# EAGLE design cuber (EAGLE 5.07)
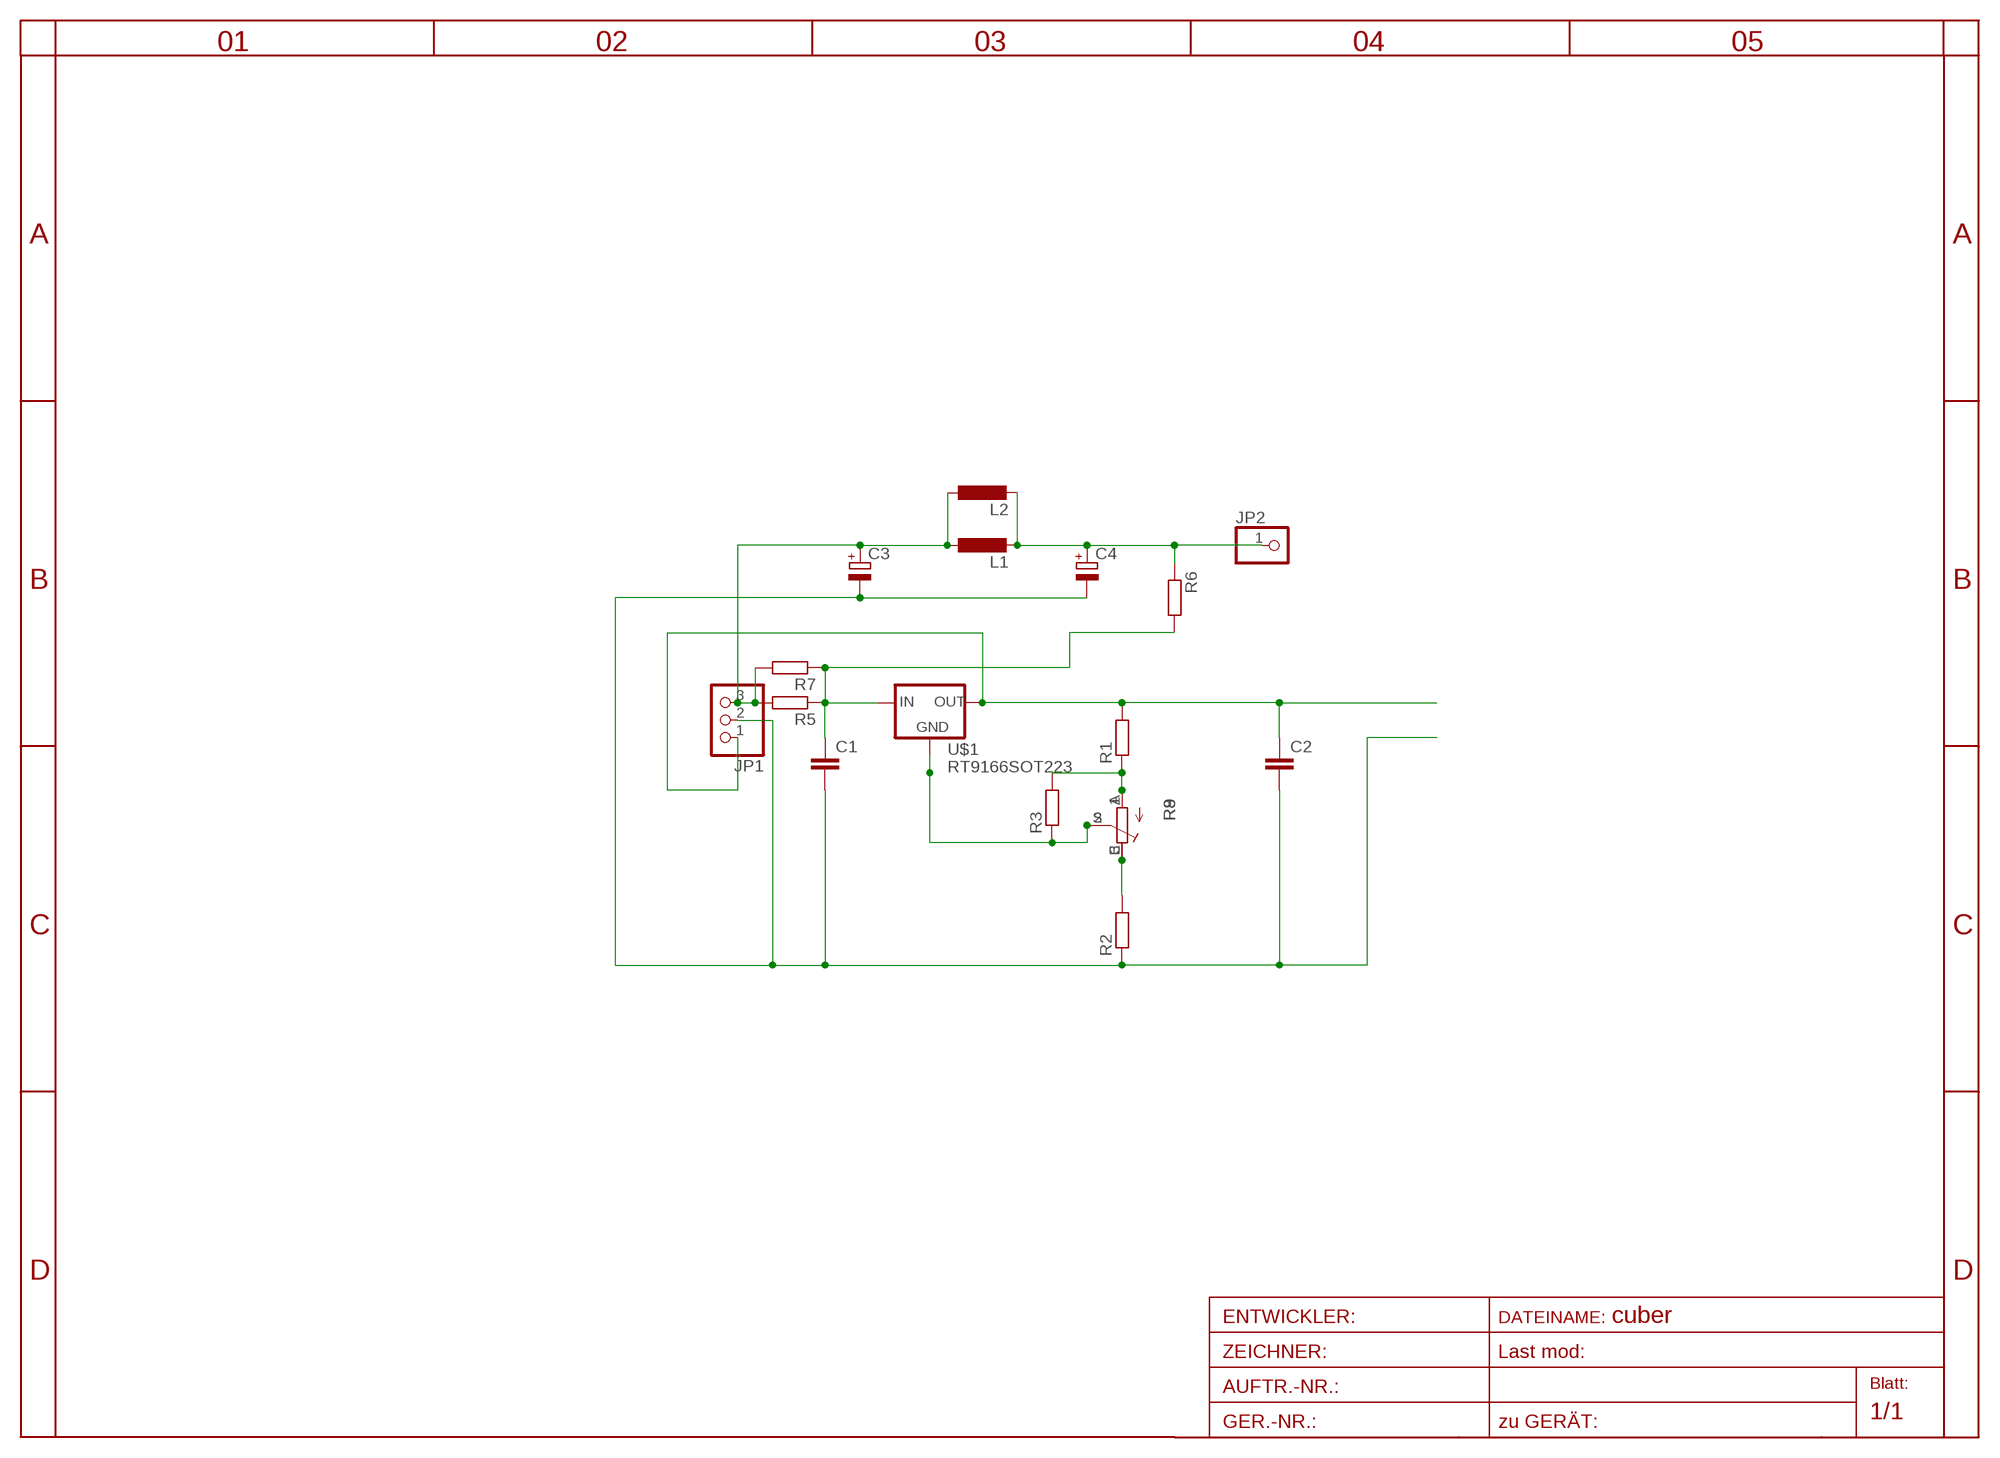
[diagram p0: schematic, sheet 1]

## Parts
C1  C-EUC1206  [C1206]
C2  C-EUC1206  [C1206]
C3  CPOL-EUE  [PANASONIC_E]
C4  CPOL-EUE  [PANASONIC_E]
JP1  PINHD-1X3  [1X03]
JP2  PINHD-1X11X0.4  [1X01]
L1  L-EUPIS2816  [PIS2816]
L2  L-EUOPEN  [OPEN5]
R1  R-EU_R0805  [R0805]
R2  R-EU_R0805  [R0805]
R3  R-EU_R0805  [R0805]
R5  R-EU_R0805  [R0805]
R6  R-EU_R0805  [R0805]
R7  R-EU_R0805  [R0805]
R8  TRIM_EU-RAND160  [RANDL]
R9  R-TRIMM3339P  [RTRIM3339P]
U$1  RT9166SOT223  [SOT223]

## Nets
ADJ: R3.1 R8.S R9.2(S) U$1.2(GND) U$1.4(GND1)
GND: C1.2 C2.2 C3.- C4.- JP1.2 R2.1
IN: C1.1 R5.1 R6.2 R7.1 U$1.3(IN)
N$1: C3.+ JP1.3 L1.1 L2.1 R5.2 R7.2
N$3: C4.+ JP2.1 L1.2 L2.2 R6.1
N$6: R2.2 R8.E R9.3(A)
N$7: R1.1 R3.2 R8.A R9.1(E)
OUT: C2.1 JP1.1 R1.2 U$1.1(OUT)

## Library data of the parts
C1 C2 = rcl:C-EU: CAPACITOR, European symbol
C3 C4 = rcl:CPOL-EU: POLARIZED CAPACITOR, European symbol
JP1 = pinhead:PINHD-1X3: PIN HEADER
JP2 = pinhead:PINHD-1X1: PIN HEADER
L1 L2 = rcl:L-EU: INDUCTOR, European symbol
R1-R3 R5-R7 = rcl:R-EU_: RESISTOR, European symbol
R8 = pot:TRIM_EU-: POTENTIOMETER
R9 = rcl:R-TRIMM: Trimm resistor
U$1 = v-reg:RT9166

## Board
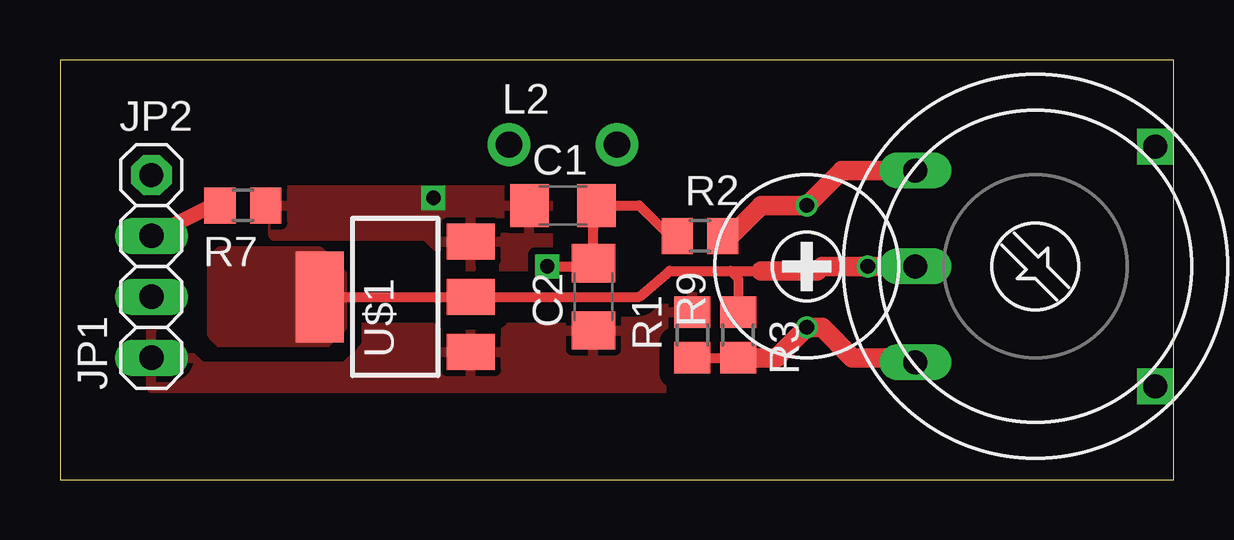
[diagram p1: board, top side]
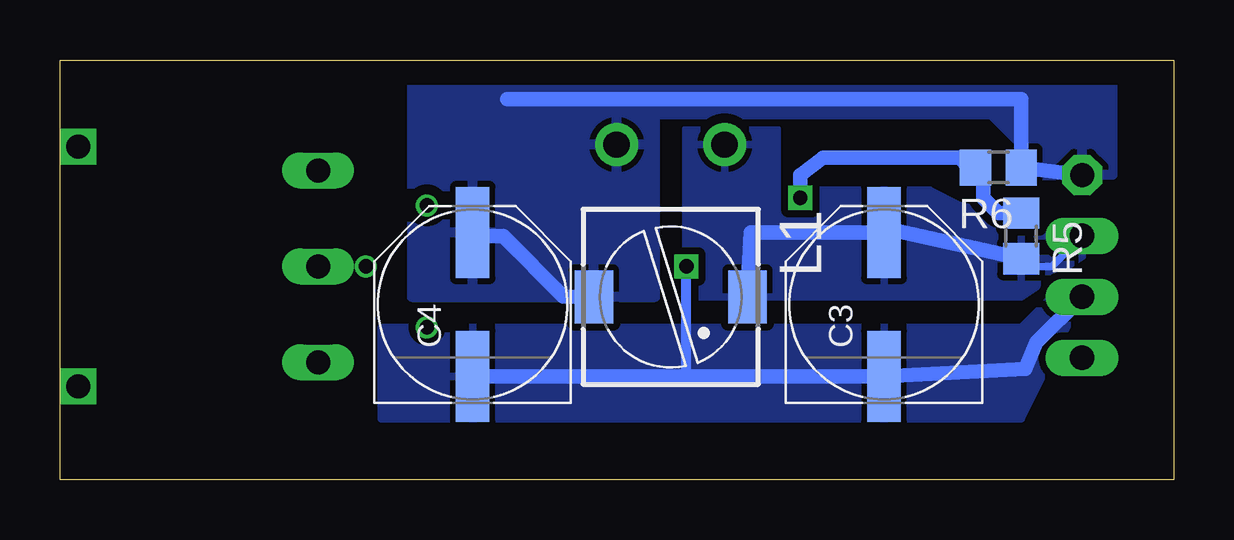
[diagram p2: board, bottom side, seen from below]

Size 46.4 x 17.5 mm. Coordinates in mm from the lower left corner, seen from the top.
Outline: 0,0 46.4,0 46.4,17.5 0,17.5 0,0
Copper layers (1*16): Top 0.035mm / dielectric 1.5mm / Bottom 0.035mm
Design rules "default *": minimum track width 10mil, minimum drill 20mil, track to track 8mil, track to pad 8mil, pad to pad 8mil, via to via 8mil, smd to smd 8mil, copper to edge 40mil, drill to drill 8mil, minimum pad ring 1mil, minimum via ring 8mil, stop-mask expansion 4mil, vias tented up to drill 0mil, thermal gap 10mil

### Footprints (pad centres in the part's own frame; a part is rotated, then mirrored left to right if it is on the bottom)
C1206 = smd 1.6 x 1.8: 1 -1.4,0; 2 1.4,0
PANASONIC_E = smd 3.8 x 1.4: + 3,0; - -3,0
1X03 = drill 1.016 long: 1 -2.54,0; 2 0,0; 3 2.54,0
1X01 = drill 1 pad 1.676 octagon: 1 0,0
PIS2816 = smd 2.2 x 1.6: 1 0,3.2; 2 0,-3.2
OPEN5 = drill 1.1 pad 1.778 round: 1 -2.25,0; 2 2.25,0
R0805 = smd 1.3 x 1.5: 1 -0.95,0; 2 0.95,0
RANDL = drill 1 long: A -4,5; E 4,5; S 0,5 | drill 1 square: P$1 -5,-5; P$2 5,-5
RTRIM3339P = drill 0.61 round: 1 -2.54,0; 2 0,-2.54; 3 2.54,0
SOT223 = smd 1.5 x 2: 1 -2.3,-3.15; 2 0,-3.15; 3 2.3,-3.15 | smd 3.8 x 2: 4 0,3.15

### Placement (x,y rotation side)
C1  20.95,11.43 0 top
C2  22.23,7.62 90 top
C3  12.06,7.3 90 bottom
C4  29.21,7.3 90 bottom
JP1  3.81,7.62 90 top
JP2  3.81,12.7 0 top
L1  20.95,7.62 270 bottom
L2  20.95,13.97 0 top
R1  26.35,6.03 90 top
R2  26.67,10.16 0 top
R3  28.26,6.03 270 top
R5  6.35,10.16 270 bottom
R6  7.3,13.02 180 bottom
R7  7.62,11.43 180 top
R8  40.64,8.89 90 top
R9  31.11,8.89 90 top
U$1  13.97,7.62 90 top

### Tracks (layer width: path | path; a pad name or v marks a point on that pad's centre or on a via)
ADJ
  Top 0.406: U$1.4 U$1.2 24.13,7.62 25.4,8.7 27.94,8.7 | 27.94,8.7 29.21,8.7 | R3.1 28.26,8.38 27.94,8.7
  Top 0.813: 29.21,8.7 31.56,8.7 31.75,8.89 R9.2 R8.S
  pour Top (no thermals): 6.35,6.03 6.35,9.21 6.67,9.53 10.79,9.53 11.75,8.57 11.75,6.35 11.11,5.71 6.67,5.71
GND  (via drill 0.6)
  Top 0.406: v20.3,8.89 21.59,8.89 21.59,9.02 C2.2 22.23,10.48 C1.2 24.13,11.43 25.4,10.16 R2.1
  Bottom 0.406: 20.3,4.3 v20.3,8.89
  Bottom 0.61: C4.- 20.3,4.3 C3.- 6.17,4.62 5.71,5.71 JP1.2
  pour Bottom (isolate 0.305, rank 3): 3.81,7.62 5.08,7.62 6.35,6.35 33.02,6.35 33.02,2.54 6.35,2.54
IN  (via drill 0.6)
  Bottom 0.61: v15.56,11.75 15.56,12.7 14.61,13.43 8.89,13.43 8.57,13.02 R6.2 7.94,12.7 7.94,11.75 7.3,11.11 R5.1
  pour Top (isolate 0.305): 20.32,12.06 20.32,8.89 16.51,8.89 15.24,10.16 8.89,10.16 8.89,12.06
N$1
  Top 0.61: R7.2 6.35,11.43 JP1.3
  Bottom 0.305: JP1.3 5.08,8.89 6.03,8.89 R5.2
  Bottom 0.61: R5.2 12.06,10.48 C3.+ 17.61,10.3 L1.1
  pour Bottom (isolate 0.305, rank 2): 2.54,10.16 6.35,7.62 20.32,7.62 20.32,14.61 16.51,14.61 16.51,12.06 10.16,12.06 8.89,11.43
N$3
  Bottom 0.61: L1.2 25.43,7.64 27.94,10.16 28.75,10.16 | 27.77,15.88 6.35,15.88 6.35,13.97 R6.1 JP2.1
  pour Bottom (isolate 0.406): 2.54,16.51 31.75,16.51 31.75,7.62 21.59,7.62 21.59,15.24 7.62,15.24 6.35,13.97 6.35,12.7 2.54,12.7
N$6
  Top 0.813: R8.E 32.58,12.89 R9.3 29.21,11.43 27.94,10.16 R2.2
N$7
  Top 0.406: R1.1 R3.2
  Top 0.813: R3.2 29.85,5.08 R9.1 31.75,6.35 33.02,5.08 35.45,5.08 R8.A
OUT
  pour Top (isolate 0.61, rank 3): 3.81,6.35 21.59,6.35 22.86,7.62 26.67,7.62 26.67,5.08 25.4,3.81 3.81,3.81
